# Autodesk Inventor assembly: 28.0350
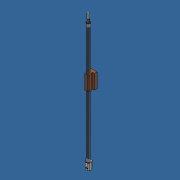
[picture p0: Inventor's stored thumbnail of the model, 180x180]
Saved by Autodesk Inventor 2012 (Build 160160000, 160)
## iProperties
Created: 2011-09
Part Number: 28.0350
Document SubType Name: Assembly
Designer: Administrator
Description: MINI ADJ UNIT FITTING KIT
Author: Administrator
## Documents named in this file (7)
- C:\Andys Backup Data\ANDY'S INVENTOR\INVENTOR LIBRARIES\PARTS LIBRARY\READY FOR USE MODULES LG\28.0350 MINI ADJ UNIT FITTING KIT.iam
- C:\Andys Backup Data\ANDY'S INVENTOR\INVENTOR LIBRARIES\PARTS LIBRARY\READY FOR USE MODULES LG\SUBCOMPONENTS\28.0350_1 MINI ADJ M8 LEADSCREW.ipt
- C:\Andys Backup Data\ANDY'S INVENTOR\INVENTOR LIBRARIES\PARTS LIBRARY\READY FOR USE MODULES LG\SUBCOMPONENTS\28.0363 M8 DISTANCE RING.ipt
- C:\Andys Backup Data\ANDY'S INVENTOR\INVENTOR LIBRARIES\PARTS LIBRARY\READY FOR USE MODULES LG\SUBCOMPONENTS\21.1975 BUSHING.ipt
- C:\Andys Backup Data\ANDY'S INVENTOR\INVENTOR LIBRARIES\PARTS LIBRARY\READY FOR USE MODULES LG\SUBCOMPONENTS\28.0361 MINI ADJ CARRIAGE.ipt
- C:\Andys Backup Data\ANDY'S INVENTOR\INVENTOR LIBRARIES\PARTS LIBRARY\READY FOR USE MODULES LG\SUBCOMPONENTS\28.0362 CLAMP BLOCK.ipt
- C:\Andys Backup Data\ANDY'S INVENTOR\INVENTOR LIBRARIES\PARTS LIBRARY\FASTENING ELEMENTS\SET SCREWS\21.1380 M6X12 SET SCREW FLAT END.ipt
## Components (8 placed, 6 different names)
1. 28.0350_1 MINI ADJ M8 LEADSCREW:1 — Insert:1, Insert:2, Mate:4
2. 28.0363 M8 DISTANCE RING:1 — Insert:1, Insert:5
3. 28.0363 M8 DISTANCE RING:2 — Insert:2, Insert:3
4. 21.1975 BUSHING:1 — Insert:3, Insert:4
5. 28.0361 MINI ADJ CARRIAGE:1 — Angle:1, Angle:2, Mate:4
6. 28.0362 CLAMP BLOCK:1 — Insert:4, Angle:2, Mate:2, Mate:3
7. 21.1380 M6X12 SET SCREW FLAT END:1 — Mate:2, Mate:3
8. 21.1975 BUSHING:2 — Insert:5
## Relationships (10: Insert 5, Mate 3, Angle 2)
- Insert:1: 28.0350_1 MINI ADJ M8 LEADSCREW:1 ↔ 28.0363 M8 DISTANCE RING:1
- Insert:2: 28.0350_1 MINI ADJ M8 LEADSCREW:1 ↔ 28.0363 M8 DISTANCE RING:2
- Insert:3: 28.0363 M8 DISTANCE RING:2 ↔ 21.1975 BUSHING:1
- Angle:1: 28.0361 MINI ADJ CARRIAGE:1
- Insert:4: 21.1975 BUSHING:1 ↔ 28.0362 CLAMP BLOCK:1
- Angle:2: 28.0361 MINI ADJ CARRIAGE:1 ↔ 28.0362 CLAMP BLOCK:1
- Mate:2: 28.0362 CLAMP BLOCK:1 ↔ 21.1380 M6X12 SET SCREW FLAT END:1
- Mate:3: 28.0362 CLAMP BLOCK:1 ↔ 21.1380 M6X12 SET SCREW FLAT END:1
- Insert:5: 28.0363 M8 DISTANCE RING:1 ↔ 21.1975 BUSHING:2
- Mate:4: 28.0350_1 MINI ADJ M8 LEADSCREW:1 ↔ 28.0361 MINI ADJ CARRIAGE:1
